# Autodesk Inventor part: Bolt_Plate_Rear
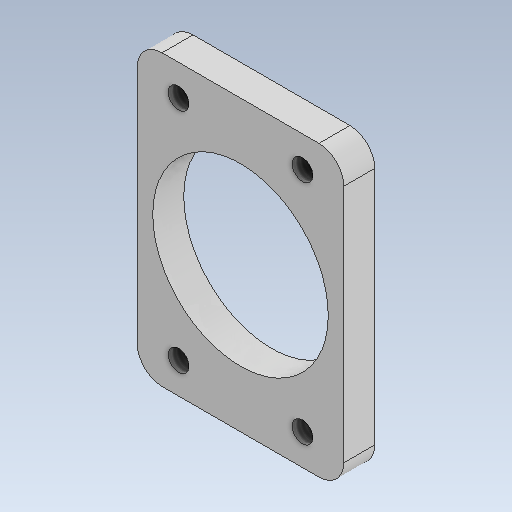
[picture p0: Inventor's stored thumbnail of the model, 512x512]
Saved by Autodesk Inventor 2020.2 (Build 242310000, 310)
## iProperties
Created: 2019-12
Part Number: Bolt_Plate_Rear
Material: Generic
Document SubType Name: Modeling
Designer: Patrick Everitt
Density: 1 g/cm^3
Appearance: Default
Description: 2 1/2 x 3/8 CRS 3.75 Lg
Author: Patrick Everitt
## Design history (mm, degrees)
sketch "Sketch1"
  geometry: L1 (-24.13, -44.45)-(24.13, -44.45); L2 (31.75, -36.83)-(31.75, 36.83); L3 (24.13, 44.45)-(-24.13, 44.45); L4 (-31.75, 36.83)-(-31.75, -36.83); C1 r 26.988 at (0, 0); A1 r 7.62 centre (-24.13, 36.83) between (-24.13, 44.45) and (-31.75, 36.83); A2 r 7.62 centre (24.13, 36.83) between (31.75, 36.83) and (24.13, 44.45); A3 r 7.62 centre (24.13, -36.83) between (24.13, -44.45) and (31.75, -36.83); A4 r 7.62 centre (-24.13, -36.83) between (-31.75, -36.83) and (-24.13, -44.45); 5 further points
  constraints: 8 end point, 8 point on circle, 8 point on line, 8 tangent, 5 centre point, 3 equal radius, 2 parallel, 1 coincident, 1 horizontal, 1 perpendicular
  dimensions: "d0" = 53.975 diameter of C1; "d34" = 7.62 radius of A1; "d35" = 88.9 distance of L1.end L3.start; "d36" = 63.5 distance of L2.end L4.start; "d37" = 31.75 horizontal distance of point (0, 0) point (31.75, 44.45) (= 0.5 x d36); "d38" = 44.45 distance from line of L3 point (0, 0) (= 0.5 x d35)
extrude "Extrusion1" new body sketch "Sketch1" distance "d17" = 9.525; taper "d18" = 0 deg
sketch "Sketch2"
  geometry: 5 further points
  dimensions: "d26" = 38.1 distance of point (19.05, 34.925) point (-19.05, 34.925) (= 2 x d27); "d27" = 19.05 horizontal distance of point (19.05, 34.925) point (0, 0); "d28" = 19.05 horizontal distance of point (0, 0) point (19.05, -34.925) (= d27); "d29" = 34.925 vertical distance of point (0, 0) point (19.05, 34.925); "d30" = 69.85 distance of point (19.05, -34.925) point (19.05, 34.925) (= 2 x d29); "d31" = 34.925 vertical distance of point (-19.05, 34.925) point (0, 0) (= d29); "d32" = 69.85 distance of point (-19.05, -34.925) point (-19.05, 34.925) (= d30); "d33" = 38.1 distance of point (19.05, -34.925) point (-19.05, -34.925) (= d26)
hole "Hole1" sketch "Sketch2" at (-19.05, 34.925), (-19.05, -34.925), (19.05, -34.925), (19.05, 34.925) diameter "d19" = 6.4008; stored, may be unused: countersink angle "d23" = 82 deg, drill point angle "d25" = 118 deg; dims "d20" = 15.875, "d21" = 9.525, "d22" = 6.35, "d24" = 22.9362
body "Solid1"
